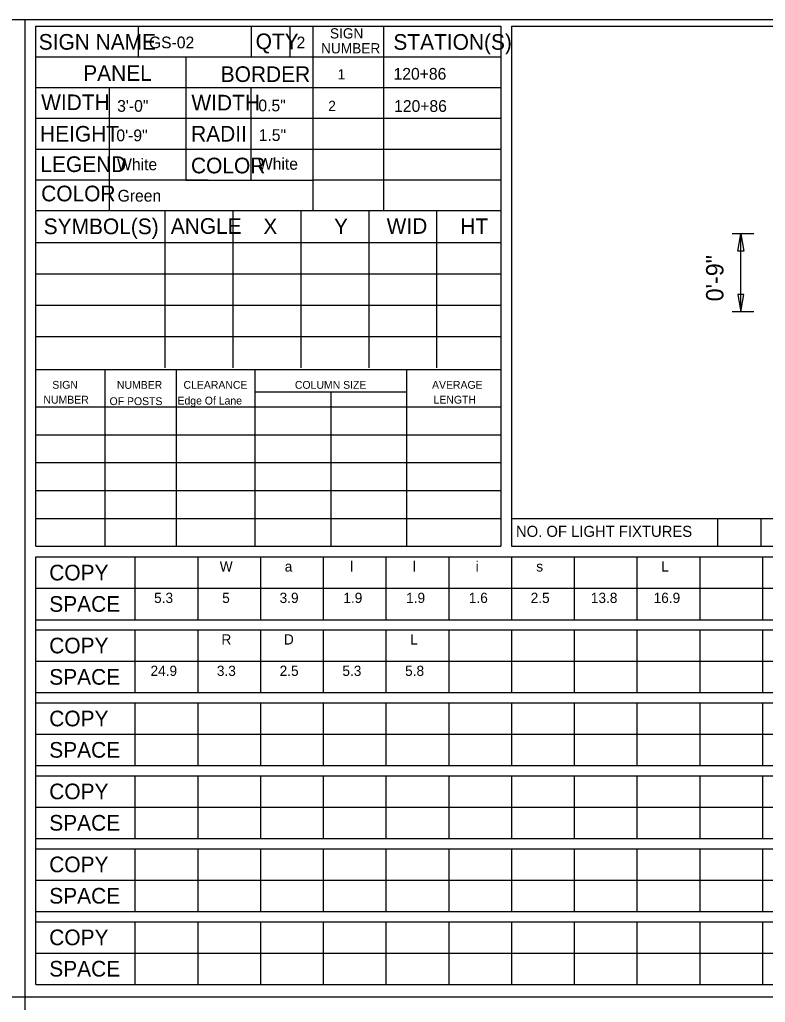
# Model space of a CAD drawing. Extents: x -875 to -645, y -2221 to -2162.
# Drawn here: x -766.2 to -759.04, y -2211.14 to -2201.72 of the extents above; entities that cross this region are included whole.
import ezdxf

# ---------------------------------------------------------------- set-up
doc = ezdxf.new("R2010")
doc.units = 0
for name, color, linetype in [('GSSign', 7, 'Continuous'), ('SheetLinesMisc2_dp', 7, 'Continuous'), ('TextMinor', 7, 'Continuous')]:
    doc.layers.add(name, color=color, linetype=linetype)

msp = doc.modelspace()

# ---------------------------------------------------------------- linework, layer by layer
at = {"layer": 'SheetLinesMisc2_dp'}
for p, q in [((-781.1882, -2201.7168), (-751.1006, -2201.7168)), ((-766.1444, -2201.7168), (-766.1444, -2220.4462)), ((-766.0417, -2206.7637), (-766.0417, -2201.7792)), ((-766.0417, -2201.7792), (-761.5805, -2201.7792)), ((-765.0583, -2201.7792), (-765.0583, -2202.0736)), ((-763.9739, -2201.7792), (-763.9739, -2202.0736)), ((-763.6034, -2201.7792), (-763.6034, -2202.0736)), ((-763.3827, -2201.7792), (-763.3827, -2203.5458)), ((-762.7038, -2201.7792), (-762.7038, -2203.5458)), ((-761.5805, -2201.7792), (-761.5805, -2206.7637)), ((-761.4775, -2201.7792), (-751.2444, -2201.7792)), ((-761.4775, -2201.7792), (-761.4775, -2206.7638)), ((-766.0417, -2202.0736), (-761.5805, -2202.0736)), ((-764.5999, -2202.0736), (-764.5999, -2203.2545)), ((-766.0417, -2202.3681), (-761.5805, -2202.3681)), ((-765.3367, -2202.3681), (-765.3367, -2203.5458)), ((-763.9777, -2202.3712), (-763.9777, -2203.2545)), ((-766.0417, -2202.6625), (-761.5805, -2202.6625)), ((-766.0417, -2202.9569), (-761.5805, -2202.9569)), ((-766.0417, -2203.2514), (-764.3872, -2203.2514)), ((-764.5999, -2203.2545), (-763.3827, -2203.2545)), ((-763.3827, -2203.2514), (-761.5805, -2203.2514)), ((-766.0417, -2203.5458), (-761.5805, -2203.5458)), ((-764.8027, -2203.5516), (-764.8027, -2205.0548)), ((-764.1509, -2203.5516), (-764.1509, -2205.0548)), ((-763.499, -2203.5516), (-763.499, -2205.0548)), ((-762.8472, -2203.5516), (-762.8472, -2205.0548)), ((-762.1953, -2203.5516), (-762.1953, -2205.0548)), ((-766.0407, -2203.8522), (-761.5805, -2203.8522)), ((-766.0407, -2204.1529), (-761.5805, -2204.1529)), ((-766.0407, -2204.4535), (-761.5805, -2204.4535)), ((-766.0407, -2204.7541), (-761.5805, -2204.7541)), ((-766.0417, -2205.0692), (-761.5805, -2205.0692)), ((-765.3797, -2205.0692), (-765.3797, -2206.7637)), ((-764.6954, -2205.0692), (-764.6954, -2206.7637)), ((-763.9399, -2205.0692), (-763.9399, -2206.7637)), ((-762.485, -2205.0692), (-762.485, -2206.7637)), ((-763.9399, -2205.2847), (-762.4861, -2205.2847)), ((-763.2095, -2205.2847), (-763.2095, -2206.7637)), ((-766.0417, -2205.4285), (-761.5805, -2205.4285)), ((-766.0417, -2205.6955), (-761.5805, -2205.6955)), ((-766.0417, -2205.9625), (-761.5805, -2205.9625)), ((-766.0417, -2206.2296), (-761.5805, -2206.2296)), ((-766.0417, -2206.4967), (-761.5805, -2206.4967)), ((-761.4775, -2206.4967), (-751.2445, -2206.4967)), ((-759.501, -2206.4967), (-759.501, -2206.7638)), ((-759.0868, -2206.4967), (-759.0868, -2206.7638)), ((-766.0417, -2206.7637), (-761.5805, -2206.7637)), ((-761.4775, -2206.7638), (-751.2444, -2206.7638)), ((-766.0416, -2210.9634), (-766.0416, -2206.8664)), ((-766.0416, -2206.8664), (-751.2444, -2206.8664)), ((-765.089, -2206.8664), (-765.089, -2207.4676)), ((-764.487, -2206.8664), (-764.487, -2207.4676)), ((-763.8853, -2206.8664), (-763.8853, -2207.4676)), ((-763.2833, -2206.8664), (-763.2833, -2207.4676)), ((-762.6811, -2206.8664), (-762.6811, -2207.4676)), ((-762.0794, -2206.8664), (-762.0794, -2207.4676)), ((-761.4775, -2206.8664), (-761.4775, -2207.4676)), ((-760.8754, -2206.8664), (-760.8754, -2207.4676)), ((-760.2735, -2206.8664), (-760.2735, -2207.4676)), ((-759.6716, -2206.8664), (-759.6716, -2207.4676)), ((-759.0695, -2206.8664), (-759.0695, -2207.4676)), ((-766.0416, -2207.167), (-751.2444, -2207.167)), ((-766.0416, -2207.4676), (-751.2444, -2207.4676)), ((-766.0416, -2207.5657), (-751.2444, -2207.5657)), ((-765.089, -2207.5657), (-765.089, -2208.1667)), ((-764.487, -2207.5657), (-764.487, -2208.1667)), ((-763.8853, -2207.5657), (-763.8853, -2208.1667)), ((-763.2833, -2207.5657), (-763.2833, -2208.1667)), ((-762.6811, -2207.5657), (-762.6811, -2208.1667)), ((-762.0794, -2207.5657), (-762.0794, -2208.1667)), ((-761.4775, -2207.5657), (-761.4775, -2208.1667)), ((-760.8754, -2207.5657), (-760.8754, -2208.1667)), ((-760.2735, -2207.5657), (-760.2735, -2208.1667)), ((-759.6716, -2207.5657), (-759.6716, -2208.1667)), ((-759.0695, -2207.5657), (-759.0695, -2208.1667)), ((-766.0416, -2207.8663), (-751.2444, -2207.8662)), ((-766.0416, -2208.1667), (-751.2444, -2208.1667)), ((-766.0416, -2208.2648), (-751.2444, -2208.2648)), ((-765.089, -2208.2648), (-765.089, -2208.8659)), ((-764.487, -2208.2648), (-764.487, -2208.8659)), ((-763.8853, -2208.2648), (-763.8853, -2208.8659)), ((-763.2833, -2208.2648), (-763.2833, -2208.8659)), ((-762.6811, -2208.2648), (-762.6811, -2208.8659)), ((-762.0794, -2208.2648), (-762.0794, -2208.8659)), ((-761.4775, -2208.2648), (-761.4775, -2208.8659)), ((-760.8754, -2208.2648), (-760.8754, -2208.8659)), ((-760.2735, -2208.2648), (-760.2735, -2208.8659)), ((-759.6716, -2208.2648), (-759.6716, -2208.8659)), ((-759.0695, -2208.2648), (-759.0695, -2208.8659)), ((-766.0416, -2208.5654), (-751.2444, -2208.5654)), ((-766.0416, -2208.8659), (-751.2444, -2208.8659)), ((-766.0416, -2208.9639), (-751.2444, -2208.9639)), ((-765.089, -2208.9639), (-765.089, -2209.5652)), ((-764.487, -2208.9639), (-764.487, -2209.5652)), ((-763.8853, -2208.9639), (-763.8853, -2209.5652)), ((-763.2833, -2208.9639), (-763.2833, -2209.5652)), ((-762.6811, -2208.9639), (-762.6811, -2209.5652)), ((-762.0794, -2208.9639), (-762.0794, -2209.5652)), ((-761.4775, -2208.9639), (-761.4775, -2209.5652)), ((-760.8754, -2208.9639), (-760.8754, -2209.5652)), ((-760.2735, -2208.9639), (-760.2735, -2209.5652)), ((-759.6716, -2208.9639), (-759.6716, -2209.5652)), ((-759.0695, -2208.9639), (-759.0695, -2209.5652)), ((-766.0416, -2209.2646), (-751.2444, -2209.2646)), ((-766.0416, -2209.5652), (-751.2444, -2209.5652)), ((-766.0416, -2209.6632), (-751.2444, -2209.6632)), ((-765.089, -2209.6632), (-765.089, -2210.2643)), ((-764.487, -2209.6632), (-764.487, -2210.2643)), ((-763.8853, -2209.6632), (-763.8853, -2210.2643)), ((-763.2833, -2209.6632), (-763.2833, -2210.2643)), ((-762.6811, -2209.6632), (-762.6811, -2210.2643)), ((-762.0794, -2209.6632), (-762.0794, -2210.2643)), ((-761.4775, -2209.6632), (-761.4775, -2210.2643)), ((-760.8754, -2209.6632), (-760.8754, -2210.2643)), ((-760.2735, -2209.6632), (-760.2735, -2210.2643)), ((-759.6716, -2209.6632), (-759.6716, -2210.2643)), ((-759.0695, -2209.6632), (-759.0695, -2210.2643)), ((-766.0416, -2209.9637), (-751.2444, -2209.9637)), ((-766.0416, -2210.2643), (-751.2444, -2210.2643)), ((-766.0416, -2210.3624), (-751.2444, -2210.3624)), ((-765.089, -2210.3624), (-765.089, -2210.9634)), ((-764.487, -2210.3624), (-764.487, -2210.9634)), ((-763.8853, -2210.3624), (-763.8853, -2210.9634)), ((-763.2833, -2210.3624), (-763.2833, -2210.9634)), ((-762.6811, -2210.3624), (-762.6811, -2210.9634)), ((-762.0794, -2210.3624), (-762.0794, -2210.9634)), ((-761.4775, -2210.3624), (-761.4775, -2210.9634)), ((-760.8754, -2210.3624), (-760.8754, -2210.9634)), ((-760.2735, -2210.3624), (-760.2735, -2210.9634)), ((-759.6716, -2210.3624), (-759.6716, -2210.9634)), ((-759.0695, -2210.3624), (-759.0695, -2210.9634)), ((-766.0416, -2210.6628), (-751.2444, -2210.6628)), ((-766.0416, -2210.9634), (-751.2444, -2210.9634)), ((-781.1882, -2211.0815), (-751.1006, -2211.0815))]:
    msp.add_line(p, q, dxfattribs=at)
at = {"layer": 'TextMinor'}
for p, q in [((-759.1526, -2203.7682), (-759.361, -2203.7682)), ((-759.2776, -2204.5182), (-759.2776, -2203.7682)), ((-759.1526, -2204.5182), (-759.361, -2204.5182))]:
    msp.add_line(p, q, dxfattribs=at)
for points in [[(-759.2776, -2203.7682), (-759.2499, -2203.9348), (-759.3054, -2203.9348)], [(-759.2776, -2204.5182), (-759.2499, -2204.3515), (-759.3054, -2204.3515)]]:
    msp.add_lwpolyline(points, close=True, dxfattribs=at)

# ---------------------------------------------------------------- texts
at = {"layer": 'GSSign'}
for s, height, p in [('GS-02', 0.11249, (-764.9553, -2201.9917)), ('2', 0.1125, (-763.539, -2201.992)), ('120+86', 0.11249, (-762.6086, -2202.2921)), ('3\'-0"', 0.11249, (-765.2596, -2202.5998)), ('0.5"', 0.11249, (-763.9051, -2202.5956)), ('120+86', 0.11249, (-762.6032, -2202.6008)), ('0\'-9"', 0.11249, (-765.2672, -2202.8823)), ('1.5"', 0.11249, (-763.9021, -2202.8792)), ('White', 0.11249, (-765.2608, -2203.1597)), ('White', 0.11249, (-763.9097, -2203.1553)), ('Green', 0.11249, (-765.2558, -2203.4605)), ('W', 0.098, (-764.2759, -2207.0067)), ('a', 0.098, (-763.6526, -2207.0067)), ('l', 0.098, (-763.0256, -2207.0067)), ('l', 0.098, (-762.4235, -2207.0067)), ('i', 0.098, (-761.8215, -2207.0067)), ('s', 0.098, (-761.2394, -2207.0067)), ('L', 0.098, (-760.0397, -2207.0067)), ('5.3', 0.09803, (-764.9058, -2207.3073)), ('5', 0.098, (-764.2525, -2207.3073)), ('3.9', 0.09803, (-763.7018, -2207.3073)), ('1.9', 0.09803, (-763.0903, -2207.3073)), ('1.9', 0.09803, (-762.4882, -2207.3073)), ('1.6', 0.09803, (-761.8865, -2207.3073)), ('2.5', 0.09803, (-761.2934, -2207.3073)), ('13.8', 0.09803, (-760.7163, -2207.3073)), ('16.9', 0.09803, (-760.1141, -2207.3073)), ('R', 0.098, (-764.2597, -2207.7059)), ('D', 0.098, (-763.6604, -2207.7059)), ('L', 0.098, (-762.448, -2207.7059)), ('24.9', 0.09803, (-764.9401, -2208.0065)), ('3.3', 0.09803, (-764.3037, -2208.0065)), ('2.5', 0.09803, (-763.7016, -2208.0065)), ('5.3', 0.09803, (-763.0996, -2208.0065)), ('5.8', 0.09803, (-762.4978, -2208.0065))]:
    msp.add_text(s, height=height, dxfattribs=at).set_placement(p)
at = {"layer": 'TextMinor'}
for s, height, p in [('SIGN NAME', 0.14999, (-766.0125, -2202.0047)), ('QTY', 0.14999, (-763.9312, -2201.9997)), ('SIGN', 0.09803, (-763.2188, -2201.8973)), ('STATION(S)', 0.14999, (-762.6102, -2202.0055)), ('NUMBER', 0.09803, (-763.3041, -2202.0399)), ('PANEL', 0.14999, (-765.5856, -2202.3038)), ('BORDER', 0.14999, (-764.2664, -2202.314)), ('  1   ', 0.09803, (-763.217, -2202.2895)), ('WIDTH', 0.14999, (-765.9888, -2202.584)), ('WIDTH', 0.14999, (-764.5473, -2202.5871)), ('  2   ', 0.09803, (-763.3078, -2202.5925)), ('HEIGHT', 0.14999, (-765.9999, -2202.8858)), ('RADII', 0.14999, (-764.5507, -2202.8853)), ('LEGEND', 0.14999, (-765.9966, -2203.177)), ('COLOR', 0.14999, (-764.5518, -2203.1898)), ('COLOR', 0.14999, (-765.9888, -2203.458)), ('SYMBOL(S)', 0.14999, (-765.9649, -2203.7727)), ('ANGLE', 0.14999, (-764.7454, -2203.7696)), ('X', 0.15, (-763.8576, -2203.7727)), ('Y', 0.15, (-763.1798, -2203.7727)), ('WID', 0.14999, (-762.675, -2203.7696)), ('HT', 0.14999, (-761.9684, -2203.7724)), ('SIGN', 0.07499, (-765.8819, -2205.2541)), ('NUMBER', 0.07499, (-765.262, -2205.255)), ('CLEARANCE', 0.07499, (-764.6234, -2205.2545)), ('COLUMN SIZE', 0.074994, (-763.5547, -2205.2545)), ('AVERAGE', 0.07499, (-762.2393, -2205.2545)), ('NUMBER', 0.07499, (-765.9672, -2205.3967)), ('OF POSTS', 0.07499, (-765.3328, -2205.4109)), ('Edge Of Lane', 0.074994, (-764.6812, -2205.4054)), ('LENGTH', 0.07499, (-762.2251, -2205.3967)), ('NO. OF LIGHT FIXTURES', 0.106291, (-761.4344, -2206.6743)), ('COPY', 0.14999, (-765.9115, -2207.0913)), ('SPACE', 0.14999, (-765.9115, -2207.392)), ('COPY', 0.14999, (-765.9115, -2207.7904)), ('SPACE', 0.14999, (-765.9115, -2208.0909)), ('COPY', 0.14999, (-765.9115, -2208.4896)), ('SPACE', 0.14999, (-765.9115, -2208.7903)), ('COPY', 0.14999, (-765.9115, -2209.1887)), ('SPACE', 0.14999, (-765.9115, -2209.4894)), ('COPY', 0.14999, (-765.9115, -2209.8881)), ('SPACE', 0.14999, (-765.9115, -2210.1887)), ('COPY', 0.14999, (-765.9115, -2210.5872)), ('SPACE', 0.14999, (-765.9115, -2210.8878))]:
    msp.add_text(s, height=height, dxfattribs=at).set_placement(p)
msp.add_text('0\'-9"', height=0.16667, rotation=90, dxfattribs=at).set_placement((-759.4443, -2204.4167))

doc.saveas('drawing.dxf')
